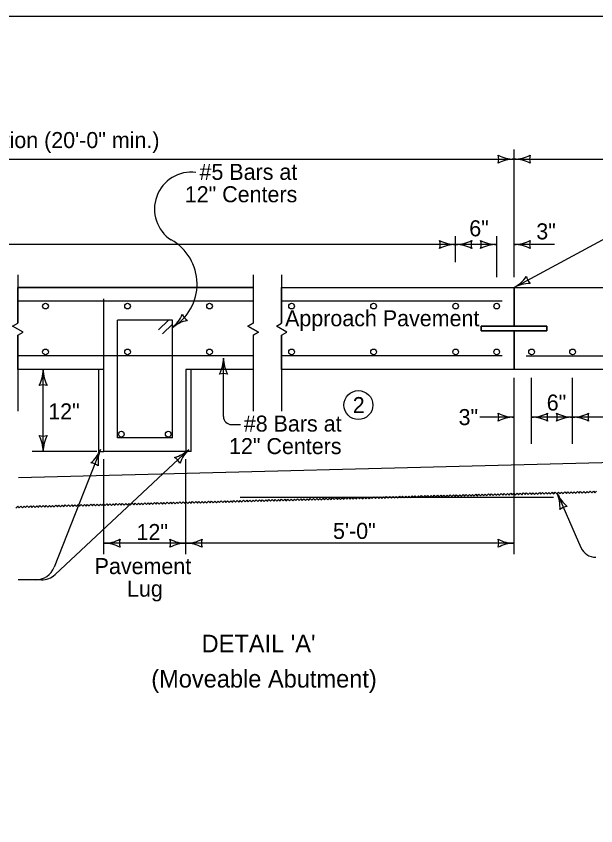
# Model space of a CAD drawing. Extents: x 10130 to 81668, y 5440 to 21644.
# Drawn here: x 11330 to 12053, y 8934 to 9944 of the extents above; entities that cross this region are included whole.
import ezdxf

# ---------------------------------------------------------------- set-up
doc = ezdxf.new("R2010")
doc.units = 0
for name, color, linetype in [('dsnStdBlockModified', 7, 'Continuous'), ('dsnStdBlockNotModified', 7, 'Continuous'), ('dsnStdBorder', 7, 'Continuous'), ('Level 3', 7, 'Continuous'), ('SheetBorder', 7, 'Continuous')]:
    doc.layers.add(name, color=color, linetype=linetype)

msp = doc.modelspace()

# ---------------------------------------------------------------- linework, layer by layer
at = {"layer": 'dsnStdBlockModified'}
for p, q in [((11951, 9618.6), (11951, 9777.8)), ((10578.7, 9765.7), (11951, 9765.7)), ((11951, 9765.7), (12919.6, 9765.7)), ((11951, 9605.5), (12114.2, 9693.9)), ((11878, 9637.2), (11878, 9669.8)), ((11929.2, 9618.6), (11929.2, 9669.8)), ((11878, 9659.2), (11252.1, 9659.2)), ((11929.2, 9659.2), (11878, 9659.2)), ((12001.4, 9659.2), (11951, 9659.2)), ((11332, 9561.1), (11332, 9605.5)), ((11332, 9605.5), (11625.4, 9605.5)), ((11625.4, 9605.5), (11625.4, 9561.1)), ((11660.9, 9561.1), (11660.9, 9605.5)), ((11660.9, 9605.5), (11951, 9605.5)), ((11660.9, 9605.5), (11951, 9605.5)), ((11951, 9605.5), (11951, 9557.2)), ((11951, 9557.2), (11951, 9605.5)), ((11951, 9605.5), (12427.4, 9605.5)), ((11951, 9605.5), (12427.4, 9605.5)), ((11951, 9557.2), (11951, 9605.5)), ((11439.4, 9428.6), (11439.4, 9591.5)), ((11660.9, 9561.1), (11660.9, 9561.1)), ((11951, 9557.2), (11910, 9557.2)), ((11910, 9557.2), (11910, 9551.5)), ((11910, 9557.2), (11910, 9551.5)), ((11991.9, 9557.2), (11951, 9557.2)), ((11991.9, 9551.5), (11991.9, 9557.2)), ((11991.9, 9551.5), (11991.9, 9557.2)), ((11332, 9503.2), (11332, 9545.9)), ((11625.4, 9545.9), (11625.4, 9503.2)), ((11660.9, 9503.2), (11660.9, 9545.9)), ((11910, 9551.5), (11951, 9551.5)), ((11991.9, 9551.5), (11910, 9551.5)), ((11951, 9551.5), (11951, 9503.2)), ((11951, 9503.2), (11951, 9551.5)), ((11951, 9551.5), (11991.9, 9551.5)), ((11951, 9503.2), (11951, 9551.5)), ((11588.5, 9444.6), (11588.5, 9517.5)), ((11439.4, 9503.2), (11332, 9503.2)), ((11363.6, 9400.9), (11363.6, 9503.2)), ((11363.6, 9474.9), (11363.6, 9503.2)), ((11439.4, 9400.9), (11439.4, 9503.2)), ((11625.4, 9503.2), (11541.7, 9503.2)), ((11541.7, 9503.2), (11541.7, 9400.9)), ((11541.7, 9503.2), (11541.7, 9400.9)), ((11951, 9503.2), (11660.9, 9503.2)), ((11951, 9503.2), (11660.9, 9503.2)), ((12427.4, 9503.2), (11951, 9503.2)), ((12427.4, 9503.2), (11951, 9503.2)), ((11951, 9272.7), (11951, 9492.7)), ((11972.7, 9410.7), (11972.7, 9492.7)), ((12023.9, 9410.7), (12023.9, 9492.7)), ((11951, 9443.7), (11908.3, 9443.7)), ((12023.9, 9443.7), (11972.7, 9443.7)), ((12846.7, 9443.7), (12023.9, 9443.7)), ((11598.6, 9434.5), (11609.8, 9434.5)), ((11363.6, 9400.9), (11363.6, 9429.2)), ((11435, 9403.5), (11377.4, 9256.7)), ((11545.3, 9403.5), (11378.4, 9247.6)), ((11332.7, 9368.4), (12427.7, 9397)), ((11430.5, 9400.9), (11349.7, 9400.9)), ((11541.7, 9400.9), (11439.4, 9400.9)), ((11439.4, 9272.7), (11439.4, 9391.5)), ((11541.7, 9272.7), (11541.7, 9391.5)), ((12004.7, 9348.9), (12034.3, 9281.1)), ((11541.7, 9286.5), (11439.4, 9286.5)), ((11951, 9286.5), (11541.7, 9286.5)), ((11361.4, 9240.8), (11332.4, 9240.8))]:
    msp.add_line(p, q, dxfattribs=at)
for points in [[(11332, 9545.9), (11338.6, 9549.7), (11325.4, 9557.3), (11332, 9561.1)], [(11625.4, 9561.1), (11618.9, 9557.3), (11632, 9549.7), (11625.4, 9545.9)], [(11660.9, 9545.9), (11667.5, 9549.7), (11654.4, 9557.3), (11660.9, 9561.1)], [(11666, 9340.4), (11667, 9339.5), (11668.9, 9341.5), (11671, 9339.6), (11672.9, 9341.6), (11674.9, 9339.7), (11676.9, 9341.7), (11678.9, 9339.8), (11680.8, 9341.8), (11682.9, 9339.9), (11684.8, 9341.9), (11686.8, 9340), (11688.8, 9342), (11690.8, 9340.1), (11692.7, 9342.1), (11694.8, 9340.2), (11696.7, 9342.2), (11698.8, 9340.3), (11700.7, 9342.3), (11702.7, 9340.4), (11704.7, 9342.4), (11706.7, 9340.5), (11708.6, 9342.5), (11710.7, 9340.6), (11712.6, 9342.6), (11713.6, 9341.7)], [(11713.6, 9341.7), (11714.6, 9340.7), (11716.6, 9342.7), (11718.6, 9340.8), (11720.5, 9342.9), (11722.6, 9340.9), (11724.5, 9343), (11726.5, 9341), (11728.5, 9343.1), (11730.5, 9341.1), (11732.4, 9343.2), (11734.5, 9341.2), (11736.4, 9343.3), (11738.4, 9341.3), (11740.4, 9343.4), (11742.4, 9341.4), (11744.3, 9343.5), (11746.4, 9341.5), (11748.3, 9343.6), (11750.3, 9341.6), (11752.3, 9343.7), (11754.3, 9341.8), (11756.2, 9343.8), (11758.3, 9341.9), (11760.2, 9343.9), (11761.2, 9342.9)], [(11761.2, 9342.9), (11762.2, 9342), (11764.2, 9344), (11766.2, 9342.1), (11768.1, 9344.1), (11770.2, 9342.2), (11772.1, 9344.2), (11774.1, 9342.3), (11776.1, 9344.3), (11778.1, 9342.4), (11780, 9344.4), (11782.1, 9342.5), (11784, 9344.5), (11786, 9342.6), (11788, 9344.6), (11790, 9342.7), (11791.9, 9344.7), (11794, 9342.8), (11795.9, 9344.8), (11797.9, 9342.9), (11799.9, 9344.9), (11801.9, 9343), (11803.8, 9345), (11805.9, 9343.1), (11807.8, 9345.1), (11808.8, 9344.2)], [(11808.8, 9344.2), (11809.8, 9343.2), (11811.8, 9345.2), (11813.8, 9343.3), (11815.7, 9345.3), (11817.8, 9343.4), (11819.7, 9345.4), (11821.7, 9343.5), (11823.7, 9345.5), (11825.7, 9343.6), (11827.6, 9345.7), (11829.7, 9343.7), (11831.6, 9345.8), (11833.6, 9343.8), (11835.6, 9345.9), (11837.6, 9343.9), (11839.5, 9346), (11841.6, 9344), (11843.5, 9346.1), (11845.5, 9344.1), (11847.5, 9346.2), (11849.5, 9344.2), (11851.4, 9346.3), (11853.5, 9344.3), (11855.4, 9346.4), (11856.4, 9345.4)], [(11856.4, 9345.4), (11857.4, 9344.4), (11859.4, 9346.5), (11861.4, 9344.6), (11863.3, 9346.6), (11865.4, 9344.7), (11867.3, 9346.7), (11869.3, 9344.8), (11871.3, 9346.8), (11873.3, 9344.9), (11875.2, 9346.9), (11877.3, 9345), (11879.2, 9347), (11881.2, 9345.1), (11883.2, 9347.1), (11885.2, 9345.2), (11887.2, 9347.2), (11889.2, 9345.3), (11891.1, 9347.3), (11893.2, 9345.4), (11895.1, 9347.4), (11897.1, 9345.5), (11899, 9347.5), (11901.1, 9345.6), (11903, 9347.6), (11904, 9346.7)], [(11904, 9346.7), (11905.1, 9345.7), (11907, 9347.7), (11909, 9345.8), (11911, 9347.8), (11913, 9345.9), (11914.9, 9347.9), (11917, 9346), (11918.9, 9348), (11920.9, 9346.1), (11922.9, 9348.1), (11924.9, 9346.2), (11926.8, 9348.2), (11928.9, 9346.3), (11930.8, 9348.3), (11932.8, 9346.4), (11934.8, 9348.4), (11936.8, 9346.5), (11938.7, 9348.6), (11940.8, 9346.6), (11942.7, 9348.7), (11944.7, 9346.7), (11946.7, 9348.8), (11948.7, 9346.8), (11950.6, 9348.9), (11951.6, 9347.9)], [(11951.6, 9347.9), (11952.7, 9346.9), (11954.6, 9349), (11956.6, 9347), (11958.6, 9349.1), (11960.6, 9347.1), (11962.5, 9349.2), (11964.6, 9347.2), (11966.5, 9349.3), (11968.5, 9347.3), (11970.5, 9349.4), (11972.5, 9347.4), (11974.4, 9349.5), (11976.5, 9347.6), (11978.4, 9349.6), (11980.4, 9347.7), (11982.4, 9349.7), (11984.4, 9347.8), (11986.3, 9349.8), (11988.4, 9347.9), (11990.3, 9349.9), (11992.3, 9348), (11994.3, 9350), (11996.3, 9348.1), (11998.2, 9350.1), (11999.3, 9349.1)], [(11999.3, 9349.1), (12000.3, 9348.2), (12002.2, 9350.2), (12004.2, 9348.3), (12006.2, 9350.3), (12008.2, 9348.4), (12010.1, 9350.4), (12012.2, 9348.5), (12014.1, 9350.5), (12016.1, 9348.6), (12018.1, 9350.6), (12020.1, 9348.7), (12022, 9350.7), (12024.1, 9348.8), (12026, 9350.8), (12028, 9348.9), (12030, 9350.9), (12032, 9349), (12033.9, 9351), (12036, 9349.1), (12037.9, 9351.1), (12039.9, 9349.2), (12041.9, 9351.2), (12043.9, 9349.3), (12045.8, 9351.3), (12046.9, 9350.4)], [(12046.9, 9350.4), (12047.9, 9349.4), (12049.8, 9351.5), (12051.8, 9349.5), (12053.8, 9351.6)], [(11333, 9331.6), (11331.8, 9332.7), (11329.7, 9330.4)], [(11332.7, 9331.7), (11333.8, 9330.8), (11335.7, 9332.8), (11337.7, 9330.9), (11339.7, 9332.9), (11341.7, 9331), (11343.6, 9333), (11345.7, 9331.1), (11347.6, 9333.1), (11349.6, 9331.2), (11351.6, 9333.2), (11353.6, 9331.3), (11355.5, 9333.3), (11357.6, 9331.4), (11359.5, 9333.4), (11361.5, 9331.5), (11363.5, 9333.5), (11365.5, 9331.6), (11367.4, 9333.6), (11369.5, 9331.7), (11371.4, 9333.7), (11373.4, 9331.8), (11375.4, 9333.8), (11377.4, 9331.9), (11379.3, 9333.9), (11380.3, 9333)], [(11380.3, 9333), (11381.4, 9332), (11383.3, 9334), (11385.3, 9332.1), (11387.3, 9334.1), (11389.3, 9332.2), (11391.2, 9334.3), (11393.3, 9332.3), (11395.2, 9334.4), (11397.2, 9332.4), (11399.2, 9334.5), (11401.2, 9332.5), (11403.1, 9334.6), (11405.2, 9332.6), (11407.1, 9334.7), (11409.1, 9332.7), (11411.1, 9334.8), (11413.1, 9332.8), (11415, 9334.9), (11417.1, 9332.9), (11419, 9335), (11421, 9333), (11423, 9335.1), (11425, 9333.2), (11426.9, 9335.2), (11428, 9334.2)], [(11428, 9334.2), (11429, 9333.3), (11430.9, 9335.3), (11432.9, 9333.4), (11434.9, 9335.4), (11436.9, 9333.5), (11438.8, 9335.5), (11440.9, 9333.6), (11442.8, 9335.6), (11444.8, 9333.7), (11446.8, 9335.7), (11448.8, 9333.8), (11450.7, 9335.8), (11452.8, 9333.9), (11454.7, 9335.9), (11456.7, 9334), (11458.7, 9336), (11460.7, 9334.1), (11462.6, 9336.1), (11464.7, 9334.2), (11466.6, 9336.2), (11468.6, 9334.3), (11470.6, 9336.3), (11472.6, 9334.4), (11474.5, 9336.4), (11475.6, 9335.5)], [(11475.6, 9335.5), (11476.6, 9334.5), (11478.5, 9336.5), (11480.5, 9334.6), (11482.5, 9336.6), (11484.5, 9334.7), (11486.4, 9336.7), (11488.5, 9334.8), (11490.4, 9336.8), (11492.4, 9334.9), (11494.4, 9336.9), (11496.4, 9335), (11498.3, 9337), (11500.4, 9335.1), (11502.3, 9337.2), (11504.4, 9335.2), (11506.3, 9337.3), (11508.3, 9335.3), (11510.2, 9337.4), (11512.3, 9335.4), (11514.2, 9337.5), (11516.3, 9335.5), (11518.2, 9337.6), (11520.2, 9335.6), (11522.2, 9337.7), (11523.2, 9336.7)], [(11523.2, 9336.7), (11524.2, 9335.7), (11526.1, 9337.8), (11528.2, 9335.8), (11530.1, 9337.9), (11532.1, 9336), (11534.1, 9338), (11536.1, 9336.1), (11538, 9338.1), (11540.1, 9336.2), (11542, 9338.2), (11544, 9336.3), (11546, 9338.3), (11548, 9336.4), (11549.9, 9338.4), (11552, 9336.5), (11553.9, 9338.5), (11555.9, 9336.6), (11557.9, 9338.6), (11559.9, 9336.7), (11561.8, 9338.7), (11563.9, 9336.8), (11565.8, 9338.8), (11567.8, 9336.9), (11569.8, 9338.9), (11570.8, 9338)], [(11570.8, 9338), (11571.8, 9337), (11573.7, 9339), (11575.8, 9337.1), (11577.7, 9339.1), (11579.7, 9337.2), (11581.7, 9339.2), (11583.7, 9337.3), (11585.6, 9339.3), (11587.7, 9337.4), (11589.6, 9339.4), (11591.6, 9337.5), (11593.6, 9339.5), (11595.6, 9337.6), (11597.5, 9339.6), (11599.6, 9337.7), (11601.5, 9339.7), (11603.5, 9337.8), (11605.5, 9339.8), (11607.5, 9337.9), (11609.4, 9340), (11611.5, 9338), (11613.4, 9340.1), (11615.4, 9338.1), (11617.4, 9340.2), (11618.4, 9339.2)], [(11618.4, 9339.2), (11619.4, 9338.2), (11621.3, 9340.3), (11623.4, 9338.3), (11625.3, 9340.4), (11627.3, 9338.4), (11629.3, 9340.5), (11631.3, 9338.5), (11633.2, 9340.6), (11635.3, 9338.6), (11637.2, 9340.7), (11639.2, 9338.7), (11641.2, 9340.8), (11643.2, 9338.9), (11645.1, 9340.9), (11647.2, 9339), (11649.1, 9341), (11651.1, 9339.1), (11653.1, 9341.1), (11655.1, 9339.2), (11657, 9341.2), (11659.1, 9339.3), (11661, 9341.3), (11663, 9339.4), (11665, 9341.4), (11666, 9340.4)]]:
    msp.add_lwpolyline(points, dxfattribs=at)
for centre, radius, start, end in [((11915.3, 9765.7), 16.4, 342.2666, 17.7333), ((11951, 9808.2), 42.5, 241.9275, 270), ((11951, 9808.2), 42.5, 270, 298.0725), ((11986.6, 9765.7), 16.4, 162.2666, 197.7334), ((11951, 9723.2), 42.5, 90, 118.0725), ((11951, 9723.2), 42.5, 61.9275, 90), ((11548.5, 9703.4), 46.1, 82.9339, 236.7669), ((11492.6, 9609.9), 63, 300.6735, 60.8331), ((11842.4, 9659.2), 16.4, 342.2666, 17.7333), ((11878, 9701.7), 42.5, 241.9275, 270), ((11878, 9616.7), 42.5, 90, 118.0725), ((11878, 9701.7), 42.5, 270, 298.0725), ((11878, 9616.7), 42.5, 61.9275, 90), ((11913.7, 9659.2), 16.4, 162.2666, 197.7334), ((11893.5, 9659.2), 16.4, 342.2666, 17.7333), ((11929.2, 9701.7), 42.5, 241.9275, 270), ((11929.2, 9616.7), 42.5, 90, 118.0725), ((11951, 9701.7), 42.5, 270, 298.0725), ((11951, 9616.7), 42.5, 61.9275, 90), ((11986.6, 9659.2), 16.4, 162.2666, 197.7334), ((11930.7, 9642.9), 42.5, 298.4258, 326.4983), ((11982.3, 9622.5), 16.4, 190.6925, 226.1592), ((11971.2, 9568.1), 42.5, 90.3533, 118.4258), ((11546, 9517.5), 42.5, 331.9275, 360), ((11631, 9517.5), 42.5, 180, 208.0725), ((11321.1, 9503.2), 42.5, 331.9275, 360), ((11406.1, 9503.2), 42.5, 180, 208.0725), ((11588.5, 9481.8), 16.4, 72.2666, 107.7334), ((11363.6, 9467.6), 16.4, 72.2666, 107.7334), ((11598.6, 9444.6), 10.1, 180, 270), ((11915.3, 9443.7), 16.4, 342.2666, 17.7333), ((11951, 9486.2), 42.5, 241.9275, 270), ((11951, 9401.2), 42.5, 90, 118.0725), ((11972.7, 9486.2), 42.5, 270, 298.0725), ((11972.7, 9401.2), 42.5, 61.9275, 90), ((12008.4, 9443.7), 16.4, 162.2666, 197.7334), ((11988.3, 9443.7), 16.4, 342.2666, 17.7333), ((12023.9, 9486.2), 42.5, 241.9275, 270), ((12023.9, 9401.2), 42.5, 90, 118.0725), ((12023.9, 9486.2), 42.5, 270, 298.0725), ((12023.9, 9401.2), 42.5, 61.9275, 90), ((12059.5, 9443.7), 16.4, 162.2666, 197.7334), ((11363.6, 9436.6), 16.4, 252.2666, 287.7333), ((11321.1, 9400.9), 42.5, 360, 28.0725), ((11406.1, 9400.9), 42.5, 151.9275, 180), ((11395.4, 9419), 42.5, 310.525, 338.5975), ((11474.5, 9388), 42.5, 158.5975, 186.67), ((11516.3, 9434.6), 42.5, 284.9817, 313.0542), ((11574.4, 9372.5), 42.5, 133.0542, 161.1266), ((11519.3, 9379.2), 16.4, 25.3208, 60.7875), ((11422, 9370.3), 16.4, 50.8642, 86.3309), ((12043.6, 9365.9), 42.5, 203.6401, 231.7126), ((11965.7, 9331.8), 42.5, 355.5676, 23.6401), ((12018.9, 9316.2), 16.4, 95.9068, 131.3735), ((11439.4, 9329), 42.5, 270, 298.0725), ((11439.4, 9244), 42.5, 61.9275, 90), ((11475.1, 9286.5), 16.4, 162.2666, 197.7334), ((11506.1, 9286.5), 16.4, 342.2666, 17.7333), ((11541.7, 9329), 42.5, 241.9275, 270), ((11541.7, 9244), 42.5, 90, 118.0725), ((11541.7, 9329), 42.5, 270, 298.0725), ((11541.7, 9244), 42.5, 61.9275, 90), ((11577.4, 9286.5), 16.4, 162.2666, 197.7334), ((11915.3, 9286.5), 16.4, 342.2666, 17.7333), ((11951, 9329), 42.5, 241.9275, 270), ((11951, 9244), 42.5, 90, 118.0725), ((12052.8, 9289.2), 20.2, 203.6401, 270)]:
    msp.add_arc(centre, radius, start, end, dxfattribs=at)
at = {"layer": 'dsnStdBlockNotModified'}
for centre, radius, start, end in [((11321.1, 9503.2), 42.5, 331.9275, 360), ((11406.1, 9503.2), 42.5, 180, 208.0725), ((11363.6, 9467.6), 16.4, 72.2666, 107.7334), ((11363.6, 9436.6), 16.4, 252.2666, 287.7333), ((11321.1, 9400.9), 42.5, 360, 28.0725), ((11406.1, 9400.9), 42.5, 151.9275, 180)]:
    msp.add_arc(centre, radius, start, end, dxfattribs=at)
at = {"layer": 'dsnStdBorder'}
for p, q in [((11332, 9621.2), (11332, 9561.1)), ((11625.4, 9621.2), (11625.4, 9561.1)), ((11660.9, 9621.2), (11660.9, 9561.1)), ((11625.4, 9605.5), (11332, 9605.5)), ((11951, 9557.2), (11951, 9605.5)), ((11625.4, 9588.5), (11332, 9588.5)), ((11935.9, 9588.5), (11660.9, 9588.5)), ((11456.5, 9418), (11456.5, 9564.7)), ((11524.7, 9564.7), (11456.5, 9564.7)), ((11519.7, 9564.7), (11507.6, 9552.7)), ((11524.7, 9418), (11524.7, 9564.7)), ((11524.7, 9559.7), (11512.6, 9547.7)), ((11910, 9551.5), (11910, 9557.2)), ((11910, 9557.2), (11991.9, 9557.2)), ((11991.9, 9557.2), (11991.9, 9551.5)), ((11332, 9545.9), (11332, 9451.3)), ((11625.4, 9545.9), (11625.4, 9451.3)), ((11660.9, 9545.9), (11660.9, 9451.3)), ((11991.9, 9551.5), (11910, 9551.5)), ((11951, 9503.2), (11951, 9551.5)), ((11625.4, 9520.3), (11332, 9520.3)), ((11935.9, 9520.3), (11660.9, 9520.3)), ((11966, 9520.3), (12427.4, 9520.3)), ((11439.4, 9503.2), (11332, 9503.2)), ((11433, 9400.9), (11433, 9503.2)), ((11439.4, 9400.9), (11439.4, 9503.2)), ((11625.4, 9503.2), (11541.7, 9503.2)), ((11548.2, 9400.9), (11548.2, 9503.2)), ((11524.7, 9418), (11456.5, 9418)), ((11433, 9400.9), (11439.4, 9400.9)), ((11541.7, 9400.9), (11439.4, 9400.9)), ((11548.2, 9400.9), (11541.7, 9400.9)), ((11609.2, 9343.8), (12000.1, 9343.8))]:
    msp.add_line(p, q, dxfattribs=at)
for points in [[(11332, 9545.9), (11338.6, 9549.7), (11325.4, 9557.3), (11332, 9561.1)], [(11625.4, 9545.9), (11632, 9549.7), (11618.9, 9557.3), (11625.4, 9561.1)], [(11660.9, 9545.9), (11667.5, 9549.7), (11654.4, 9557.3), (11660.9, 9561.1)]]:
    msp.add_lwpolyline(points, dxfattribs=at)
msp.add_circle((11756.7, 9458.9), 18, dxfattribs=at)
for centre, radius, start, end in [((11498.1, 9588.9), 42.5, 308.6676, 336.7401), ((11552.5, 9578), 16.4, 200.9342, 236.4009), ((11551.2, 9522.5), 42.5, 100.5951, 128.6676), ((11354.2, 9265.8), 25, 270, 338.5975), ((11361.4, 9265.8), 25, 270, 313.0542)]:
    msp.add_arc(centre, radius, start, end, dxfattribs=at)
at = {"layer": 'Level 3'}
for centre in [(11366.5, 9582.3), (11468.8, 9582.3), (11571.1, 9582.3), (11673.4, 9582.3), (11775.7, 9582.3), (11878, 9582.3), (11929.2, 9582.3), (11366.5, 9525.2), (11468.8, 9525.2), (11571.1, 9525.2), (11673.4, 9525.2), (11775.7, 9525.2), (11878, 9525.2), (11929.2, 9525.2), (11972.7, 9525.2), (12023.9, 9525.2), (11461.1, 9422.6), (11519.6, 9422.6)]:
    msp.add_circle(centre, 3.55, dxfattribs=at)
at = {"layer": 'SheetBorder'}
msp.add_lwpolyline([(10132.5, 9944), (13267.5, 9944), (13267.5, 7924), (10132.5, 7924)], close=True, dxfattribs=at)

# ---------------------------------------------------------------- texts
at = {"layer": 'dsnStdBlockModified'}
for s, height, p in [('Double Reinforced Section (20\'-0" min.)', 20, (11039.2, 9779.5)), ('#5 Bars at', 20, (11558.6, 9739.8)), ('12" Centers', 20, (11540.2, 9711.9)), ('6"', 20, (11895, 9669.4)), ('3"', 20, (11978.6, 9665.6)), ('Approach Pavement', 20, (11665.3, 9557.2)), ('2', 20, (11749.7, 9448.9)), ('6"', 20, (11991.6, 9452)), ('12"', 20, (11369.9, 9441)), ('3"', 20, (11881.7, 9433.9)), ('#8 Bars at', 20, (11613.8, 9425.8)), ('12" Centers', 20, (11595.4, 9397.7)), ('5\'-0"', 20, (11725.1, 9291.9)), ('12"', 20, (11480, 9290.5)), ('Pavement', 20, (11427.8, 9248)), ('Lug', 20, (11468.2, 9219.9)), ('(Moveable Abutment)', 22, (11498.4, 9106.5))]:
    msp.add_text(s, height=height, dxfattribs=at).set_placement(p)
at = {"layer": 'dsnStdBorder'}
msp.add_text("DETAIL 'A' ", height=22, dxfattribs=at).set_placement((11561.2, 9150.4))

doc.saveas('drawing.dxf')
